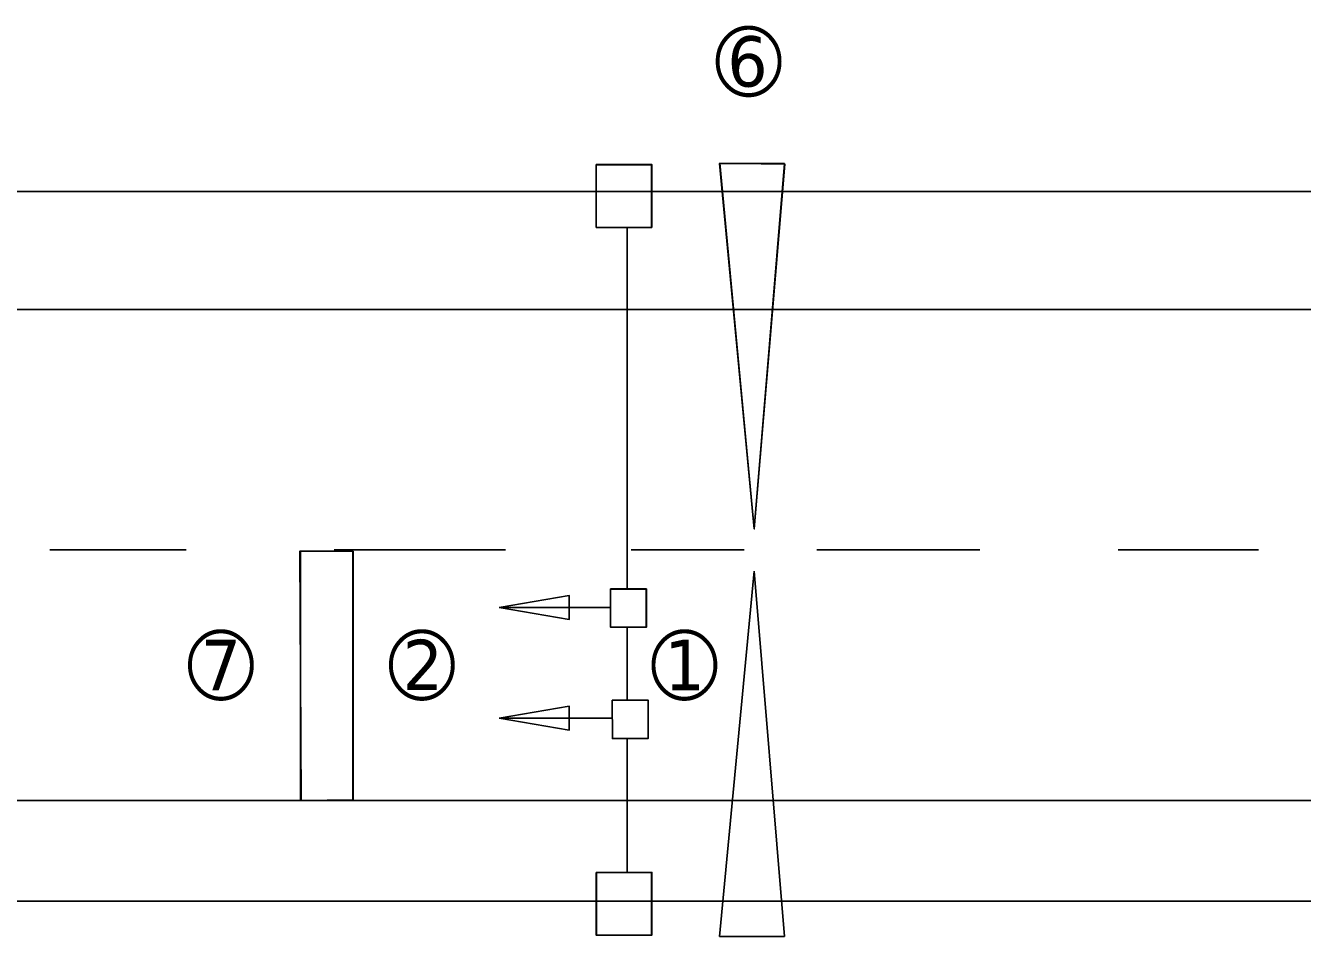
# Model space of a CAD drawing. Extents: x 10000 to 10825, y 10000 to 10530.
# Drawn here: x 10110.6 to 10181.7, y 10402.8 to 10453.5 of the extents above; entities that cross this region are included whole.
import ezdxf

# ---------------------------------------------------------------- set-up
doc = ezdxf.new("R2010")
doc.units = 0
for name, color, linetype in [('Default', 7, 'Continuous'), ('Dimension', 7, 'Continuous'), ('TextStructures', 7, 'Continuous')]:
    doc.layers.add(name, color=color, linetype=linetype)

msp = doc.modelspace()

# ---------------------------------------------------------------- linework, layer by layer
at = {"layer": 'Default'}
for p, q in [((10149.219, 10445.827), (10152.831, 10445.827)), ((10151.148, 10425.5), (10149.219, 10445.827)), ((10150.211, 10445.827), (10149.224, 10445.827)), ((10152.831, 10445.827), (10151.148, 10425.5)), ((10151.148, 10425.5), (10152.828, 10445.791)), ((10049.563, 10444.263), (10394.364, 10444.263)), ((10144.074, 10442.272), (10144.074, 10422.151)), ((10049.563, 10437.701), (10394.364, 10437.701)), ((10111.938, 10424.324), (10119.521, 10424.324)), ((10127.762, 10424.324), (10137.293, 10424.324)), ((10144.287, 10424.324), (10150.581, 10424.324)), ((10154.633, 10424.324), (10163.711, 10424.324)), ((10171.409, 10424.324), (10179.218, 10424.324)), ((10151.148, 10423.147), (10149.219, 10402.821)), ((10151.148, 10423.147), (10149.219, 10402.821)), ((10152.831, 10402.821), (10151.148, 10423.147)), ((10152.831, 10402.821), (10151.148, 10423.147)), ((10143.147, 10421.123), (10136.945, 10421.123)), ((10144.074, 10420.024), (10144.074, 10415.963)), ((10143.256, 10414.966), (10136.945, 10414.966)), ((10144.074, 10413.836), (10144.074, 10406.375)), ((10049.563, 10410.382), (10394.364, 10410.382)), ((10049.563, 10404.79), (10394.364, 10404.79)), ((10149.219, 10402.821), (10152.831, 10402.821)), ((10149.219, 10402.821), (10152.831, 10402.821))]:
    msp.add_line(p, q, dxfattribs=at)
for points in [[(10142.353, 10445.763), (10145.454, 10445.763), (10145.441, 10442.274), (10142.353, 10442.274)], [(10142.357, 10442.272), (10142.357, 10445.758), (10145.437, 10445.758), (10145.437, 10442.272)], [(10149.223, 10445.84), (10152.845, 10445.79), (10151.148, 10425.5)], [(10125.926, 10410.388), (10128.804, 10410.425), (10128.804, 10424.25), (10125.854, 10424.25)], [(10128.821, 10410.382), (10128.821, 10424.257), (10125.897, 10424.257), (10125.897, 10410.382)], [(10143.147, 10420.024), (10143.147, 10422.151), (10145.14, 10422.151), (10145.14, 10420.024)], [(10143.153, 10422.16), (10145.143, 10422.16), (10145.143, 10420.029), (10143.153, 10420.029)], [(10143.247, 10415.963), (10145.247, 10415.963), (10145.247, 10413.84), (10143.253, 10413.833)], [(10145.247, 10413.84), (10145.247, 10415.963), (10143.247, 10415.963), (10143.253, 10413.833)], [(10142.357, 10406.375), (10142.357, 10402.89), (10145.437, 10402.89), (10145.437, 10406.375)], [(10142.368, 10406.384), (10145.448, 10406.384), (10145.438, 10402.892), (10142.368, 10402.892)]]:
    msp.add_lwpolyline(points, close=True, dxfattribs=at)
for points in [[(10145.437, 10442.274), (10145.437, 10445.758), (10142.357, 10445.758), (10142.357, 10442.274)], [(10149.224, 10445.827), (10151.148, 10425.5)], [(10152.828, 10445.791), (10150.211, 10445.827)], [(10142.357, 10442.274), (10145.437, 10442.274)], [(10128.804, 10424.257), (10125.897, 10424.257), (10125.897, 10415.889)], [(10125.926, 10410.388), (10128.804, 10410.425), (10128.804, 10424.25)], [(10145.14, 10420.029), (10145.14, 10422.151), (10143.147, 10422.151), (10143.147, 10420.029)], [(10143.153, 10420.029), (10145.14, 10420.029)], [(10125.897, 10415.889), (10125.926, 10410.388)], [(10145.437, 10402.892), (10145.437, 10406.375), (10142.368, 10406.375)], [(10142.368, 10406.375), (10142.368, 10402.892), (10145.437, 10402.892)]]:
    msp.add_lwpolyline(points, dxfattribs=at)
at = {"layer": 'Dimension'}
for points in [[(10136.945, 10421.123), (10140.85, 10420.461), (10140.85, 10421.784)], [(10136.945, 10414.966), (10140.85, 10414.305), (10140.85, 10415.628)]]:
    msp.add_lwpolyline(points, close=True, dxfattribs=at)

# ---------------------------------------------------------------- texts
at = {"layer": 'TextStructures'}
for s, p in [('➅', (10148.982, 10449.759)), ('➆', (10119.61, 10416.174)), ('➁', (10130.795, 10416.174)), ('➀', (10145.411, 10416.174))]:
    msp.add_text(s, height=3.5, dxfattribs=at).set_placement(p)

doc.saveas('drawing.dxf')
